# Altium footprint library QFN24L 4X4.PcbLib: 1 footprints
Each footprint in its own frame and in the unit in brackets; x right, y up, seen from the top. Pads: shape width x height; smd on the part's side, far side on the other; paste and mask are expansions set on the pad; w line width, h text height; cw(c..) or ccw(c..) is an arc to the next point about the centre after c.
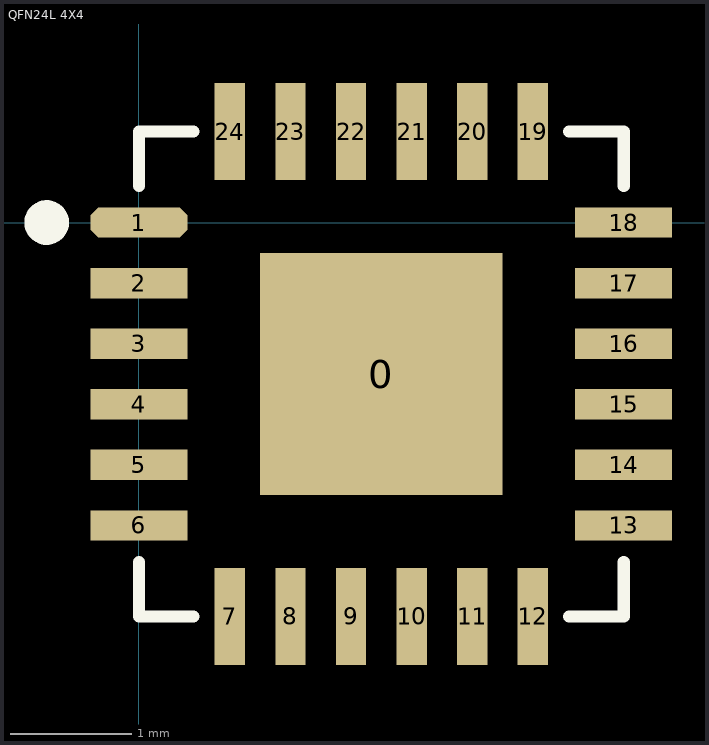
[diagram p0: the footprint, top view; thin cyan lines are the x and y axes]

## QFN24L 4X4 [mm] "QFN, 24-Leads, Body 4.1x4.1mm (max), Pitch 0.50mm, IPC Low Density"
height 0.8
pads (25):
  rect 2x2 smd: 0(2,-1.25)
  oct 0.8x0.25 smd: 1(0,0)
  rect 0.8x0.25 smd: 2(0,-0.5) 3(0,-1) 4(0,-1.5) 5(0,-2) 6(0,-2.5) 13(4,-2.5) 14(4,-2) 15(4,-1.5) 16(4,-1) 17(4,-0.5) 18(4,0)
  rect 0.25x0.8 smd: 7(0.75,-3.25) 8(1.25,-3.25) 9(1.75,-3.25) 10(2.25,-3.25) 11(2.75,-3.25) 12(3.25,-3.25) 19(3.25,0.75) 20(2.75,0.75) 21(2.25,0.75) 22(1.75,0.75) 23(1.25,0.75) 24(0.75,0.75)
Top Overlay:
  circle w0.19: c-0.762,0 r0.089
  lines w0.1: 0,-2.8 0,-3.25 0.45,-3.25 ; 0,0.3 0,0.75 0.45,0.75 ; 3.55,-3.25 4,-3.25 4,-2.8 ; 3.55,0.75 4,0.75 4,0.3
